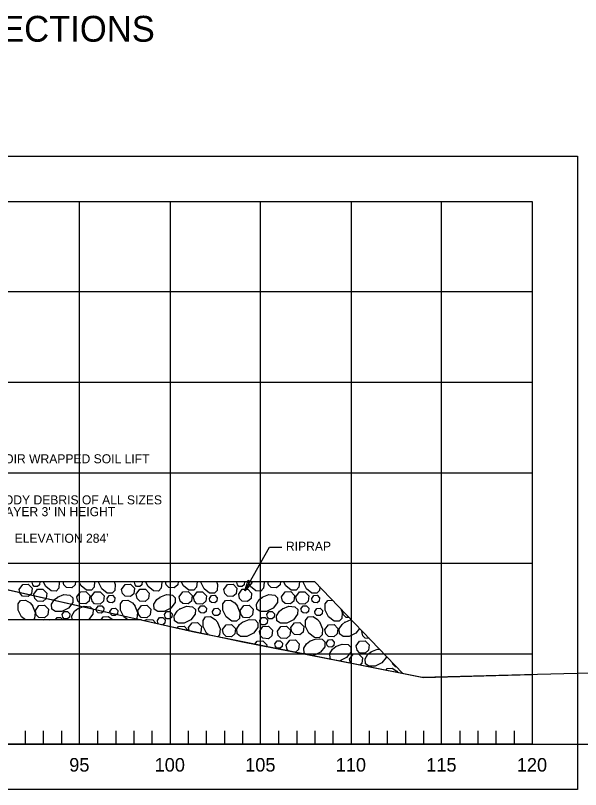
# Model space of a CAD drawing. Extents: x 1578769 to 1579225, y 724002 to 724828.
# Drawn here: x 1578895.66 to 1578926.86, y 724300.65 to 724343.43 of the extents above; entities that cross this region are included whole.
import ezdxf

# ---------------------------------------------------------------- set-up
doc = ezdxf.new("R2010")
doc.units = 0
for name, color, linetype in [('1', 7, 'Continuous'), ('Default', 7, 'Continuous'), ('Old_Level_1', 7, 'Continuous'), ('Old_Level_41', 7, 'Continuous'), ('Old_Level_42', 7, 'Continuous'), ('R_Exist Surface', 7, 'Continuous'), ('R_Rip-Rap', 7, 'Continuous')]:
    doc.layers.add(name, color=color, linetype=linetype)

msp = doc.modelspace()

# ---------------------------------------------------------------- linework, layer by layer
at = {"layer": '1'}
msp.add_lwpolyline([(1578908.325, 724311.631), (1578909.693, 724314.045), (1578910.378, 724314.045)], dxfattribs=at)
msp.add_lwpolyline([(1578908.725, 724312.094), (1578908.325, 724311.631), (1578908.516, 724312.212)], close=True, dxfattribs=at)
at = {"layer": 'Default'}
msp.add_line((1578824.194, 724303.15), (1579224.194, 724303.15), dxfattribs=at)
msp.add_lwpolyline([(1578822.944, 724322.15), (1578824.354, 724322.105), (1578827.254, 724322.088), (1578831.424, 724322.063), (1578836.824, 724322.031), (1578858.594, 724322.068), (1578861.134, 724322.067), (1578862.944, 724322.071), (1578882.454, 724322.012), (1578884.524, 724320.413), (1578890.394, 724312.796), (1578905.444, 724309.389), (1578918.124, 724306.852), (1578923.764, 724306.998), (1578939.004, 724307.393), (1578947.244, 724307.607), (1578961.874, 724307.852), (1578966.594, 724307.868), (1579023.724, 724312.412), (1579059.084, 724315.375), (1579126.244, 724320.038), (1579145.794, 724321.276)], dxfattribs=at)
at = {"layer": 'Old_Level_1'}
for points in [[(1578819.194, 724335.65), (1578926.694, 724335.65), (1578926.694, 724300.65), (1578819.194, 724300.65)], [(1578824.194, 724333.15), (1578924.194, 724333.15), (1578924.194, 724303.15), (1578824.194, 724303.15)]]:
    msp.add_lwpolyline(points, close=True, dxfattribs=at)
at = {"layer": 'Old_Level_41'}
for p, q in [((1578899.194, 724303.15), (1578899.194, 724333.15)), ((1578904.194, 724333.15), (1578904.194, 724303.15)), ((1578909.194, 724303.15), (1578909.194, 724333.15)), ((1578914.194, 724333.15), (1578914.194, 724303.15)), ((1578919.194, 724303.15), (1578919.194, 724333.15))]:
    msp.add_line(p, q, dxfattribs=at)
for points in [[(1578924.194, 724328.15), (1578824.194, 724328.15)], [(1578924.194, 724323.15), (1578824.194, 724323.15)], [(1578824.194, 724318.15), (1578924.194, 724318.15)], [(1578924.194, 724313.15), (1578824.194, 724313.15)], [(1578824.194, 724308.15), (1578924.194, 724308.15)]]:
    msp.add_lwpolyline(points, dxfattribs=at)
at = {"layer": 'Old_Level_42'}
for p, q in [((1578896.194, 724303.9), (1578896.194, 724303.15)), ((1578897.194, 724303.9), (1578897.194, 724303.15)), ((1578898.194, 724303.9), (1578898.194, 724303.15)), ((1578900.194, 724303.9), (1578900.194, 724303.15)), ((1578901.194, 724303.9), (1578901.194, 724303.15)), ((1578902.194, 724303.9), (1578902.194, 724303.15)), ((1578903.194, 724303.9), (1578903.194, 724303.15)), ((1578905.194, 724303.9), (1578905.194, 724303.15)), ((1578906.194, 724303.9), (1578906.194, 724303.15)), ((1578907.194, 724303.9), (1578907.194, 724303.15)), ((1578908.194, 724303.9), (1578908.194, 724303.15)), ((1578910.194, 724303.9), (1578910.194, 724303.15)), ((1578911.194, 724303.9), (1578911.194, 724303.15)), ((1578912.194, 724303.9), (1578912.194, 724303.15)), ((1578913.194, 724303.9), (1578913.194, 724303.15)), ((1578915.194, 724303.9), (1578915.194, 724303.15)), ((1578916.194, 724303.9), (1578916.194, 724303.15)), ((1578917.194, 724303.9), (1578917.194, 724303.15)), ((1578918.194, 724303.9), (1578918.194, 724303.15)), ((1578920.194, 724303.9), (1578920.194, 724303.15)), ((1578921.194, 724303.9), (1578921.194, 724303.15)), ((1578922.194, 724303.9), (1578922.194, 724303.15)), ((1578923.194, 724303.9), (1578923.194, 724303.15))]:
    msp.add_line(p, q, dxfattribs=at)
at = {"layer": 'R_Exist Surface'}
msp.add_lwpolyline([(1578824.194, 724322.162), (1578829.284, 724322.091), (1578836.275, 724322.056), (1578841.243, 724322.049), (1578852.243, 724322.048), (1578866.252, 724322.093), (1578877.209, 724322.014), (1578882.216, 724322.036), (1578883.229, 724321.428), (1578884.216, 724320.636), (1578885.259, 724319.504), (1578887.377, 724316.691), (1578890.502, 724312.788), (1578895.252, 724311.694), (1578904.139, 724309.679), (1578908.201, 724308.813), (1578914.491, 724307.577), (1578918.186, 724306.844), (1578924.194, 724307.012)], dxfattribs=at)
at = {"layer": 'R_Rip-Rap'}
for p, q in [((1578893.271, 724312.15), (1578912.174, 724312.15)), ((1578896.581, 724312.101), (1578896.616, 724312.15)), ((1578902.234, 724312.101), (1578902.269, 724312.15)), ((1578907.888, 724312.101), (1578907.922, 724312.15)), ((1578912.174, 724312.15), (1578917.048, 724307.07)), ((1578902.612, 724310.025), (1578889.194, 724310.025)), ((1578902.612, 724310.025), (1578902.612, 724310.025)), ((1578913.859, 724309.906), (1578914.198, 724310.041)), ((1578905.248, 724309.443), (1578905.219, 724309.595)), ((1578914.789, 724309.384), (1578914.806, 724309.407)), ((1578914.155, 724307.643), (1578914.113, 724307.861))]:
    msp.add_line(p, q, dxfattribs=at)
for points in [[(1578897.001, 724312.15), (1578897.008, 724312.142), (1578896.99, 724311.957), (1578896.876, 724311.862), (1578896.694, 724311.875), (1578896.609, 724311.958), (1578896.581, 724312.101)], [(1578898.063, 724312.15), (1578898.08, 724312.108), (1578898.051, 724311.778), (1578897.902, 724311.621), (1578897.634, 724311.626), (1578897.33, 724311.864), (1578897.187, 724312.15)], [(1578898.983, 724312.15), (1578898.963, 724311.956), (1578898.774, 724311.798), (1578898.471, 724311.82), (1578898.329, 724311.958), (1578898.291, 724312.15)], [(1578900.031, 724312.15), (1578900.003, 724311.825), (1578899.854, 724311.668), (1578899.586, 724311.673), (1578899.282, 724311.911), (1578899.162, 724312.15)], [(1578901.103, 724312.15), (1578901.171, 724311.98), (1578901.142, 724311.65), (1578900.993, 724311.493), (1578900.725, 724311.498), (1578900.421, 724311.737), (1578900.237, 724312.105), (1578900.236, 724312.15)], [(1578902.654, 724312.15), (1578902.661, 724312.142), (1578902.643, 724311.957), (1578902.529, 724311.862), (1578902.348, 724311.875), (1578902.262, 724311.958), (1578902.234, 724312.101)], [(1578903.717, 724312.15), (1578903.733, 724312.108), (1578903.705, 724311.778), (1578903.555, 724311.621), (1578903.288, 724311.626), (1578902.983, 724311.864), (1578902.84, 724312.15)], [(1578904.636, 724312.15), (1578904.617, 724311.956), (1578904.427, 724311.798), (1578904.125, 724311.82), (1578903.982, 724311.958), (1578903.945, 724312.15)], [(1578905.685, 724312.15), (1578905.657, 724311.825), (1578905.508, 724311.668), (1578905.24, 724311.673), (1578904.935, 724311.911), (1578904.816, 724312.15)], [(1578906.757, 724312.15), (1578906.824, 724311.98), (1578906.796, 724311.65), (1578906.646, 724311.493), (1578906.379, 724311.498), (1578906.074, 724311.737), (1578905.89, 724312.105), (1578905.89, 724312.15)], [(1578908.308, 724312.15), (1578908.315, 724312.142), (1578908.296, 724311.957), (1578908.183, 724311.862), (1578908.001, 724311.875), (1578907.916, 724311.958), (1578907.888, 724312.101)], [(1578909.37, 724312.15), (1578909.387, 724312.108), (1578909.358, 724311.778), (1578909.209, 724311.621), (1578908.941, 724311.626), (1578908.637, 724311.864), (1578908.494, 724312.15)], [(1578910.29, 724312.15), (1578910.27, 724311.956), (1578910.081, 724311.798), (1578909.778, 724311.82), (1578909.636, 724311.958), (1578909.598, 724312.15)], [(1578911.338, 724312.15), (1578911.31, 724311.825), (1578911.161, 724311.668), (1578910.893, 724311.673), (1578910.589, 724311.911), (1578910.469, 724312.15)], [(1578912.466, 724311.846), (1578912.449, 724311.65), (1578912.3, 724311.493), (1578912.032, 724311.498), (1578911.728, 724311.737), (1578911.544, 724312.105), (1578911.543, 724312.15)], [(1578895.867, 724311.712), (1578896.059, 724311.985), (1578896.366, 724312.002), (1578896.579, 724311.781), (1578896.548, 724311.472), (1578896.359, 724311.314), (1578896.056, 724311.336), (1578895.913, 724311.474), (1578895.867, 724311.712)], [(1578896.679, 724311.44), (1578896.871, 724311.714), (1578897.177, 724311.731), (1578897.391, 724311.51), (1578897.36, 724311.2), (1578897.17, 724311.043), (1578896.868, 724311.065), (1578896.725, 724311.203), (1578896.679, 724311.44)], [(1578901.521, 724311.712), (1578901.713, 724311.985), (1578902.019, 724312.002), (1578902.232, 724311.781), (1578902.202, 724311.472), (1578902.012, 724311.314), (1578901.709, 724311.336), (1578901.567, 724311.474), (1578901.521, 724311.712)], [(1578902.332, 724311.44), (1578902.524, 724311.714), (1578902.831, 724311.731), (1578903.044, 724311.51), (1578903.013, 724311.2), (1578902.824, 724311.043), (1578902.521, 724311.065), (1578902.379, 724311.203), (1578902.332, 724311.44)], [(1578907.174, 724311.712), (1578907.366, 724311.985), (1578907.673, 724312.002), (1578907.886, 724311.781), (1578907.855, 724311.472), (1578907.666, 724311.314), (1578907.363, 724311.336), (1578907.22, 724311.474), (1578907.174, 724311.712)], [(1578907.986, 724311.44), (1578908.178, 724311.714), (1578908.484, 724311.731), (1578908.698, 724311.51), (1578908.667, 724311.2), (1578908.477, 724311.043), (1578908.174, 724311.065), (1578908.032, 724311.203), (1578907.986, 724311.44)], [(1578897.98, 724311.28), (1578898.339, 724311.422), (1578898.669, 724311.394), (1578898.826, 724311.245), (1578898.821, 724310.977), (1578898.583, 724310.673), (1578898.215, 724310.489), (1578897.868, 724310.482), (1578897.673, 724310.621), (1578897.654, 724310.897), (1578897.813, 724311.144), (1578897.994, 724311.289)], [(1578899.051, 724311.305), (1578899.243, 724311.578), (1578899.55, 724311.596), (1578899.763, 724311.375), (1578899.732, 724311.065), (1578899.543, 724310.907), (1578899.24, 724310.929), (1578899.097, 724311.067), (1578899.051, 724311.305)], [(1578899.841, 724311.293), (1578900.033, 724311.567), (1578900.34, 724311.584), (1578900.553, 724311.363), (1578900.522, 724311.053), (1578900.333, 724310.896), (1578900.03, 724310.918), (1578899.888, 724311.056), (1578899.841, 724311.293)], [(1578900.715, 724311.209), (1578900.83, 724311.373), (1578901.014, 724311.383), (1578901.142, 724311.251), (1578901.124, 724311.065), (1578901.01, 724310.97), (1578900.828, 724310.984), (1578900.743, 724311.066), (1578900.715, 724311.209)], [(1578903.633, 724311.28), (1578903.992, 724311.422), (1578904.322, 724311.394), (1578904.479, 724311.245), (1578904.474, 724310.977), (1578904.236, 724310.673), (1578903.868, 724310.489), (1578903.521, 724310.482), (1578903.326, 724310.621), (1578903.308, 724310.897), (1578903.466, 724311.144), (1578903.647, 724311.289)], [(1578904.704, 724311.305), (1578904.896, 724311.578), (1578905.203, 724311.596), (1578905.416, 724311.375), (1578905.385, 724311.065), (1578905.196, 724310.907), (1578904.893, 724310.929), (1578904.751, 724311.067), (1578904.705, 724311.305)], [(1578905.495, 724311.293), (1578905.687, 724311.567), (1578905.993, 724311.584), (1578906.207, 724311.363), (1578906.176, 724311.053), (1578905.986, 724310.896), (1578905.683, 724310.918), (1578905.541, 724311.056), (1578905.495, 724311.293)], [(1578906.369, 724311.209), (1578906.484, 724311.373), (1578906.668, 724311.383), (1578906.796, 724311.251), (1578906.777, 724311.065), (1578906.664, 724310.97), (1578906.482, 724310.984), (1578906.396, 724311.066), (1578906.369, 724311.209)], [(1578909.286, 724311.28), (1578909.646, 724311.422), (1578909.976, 724311.394), (1578910.133, 724311.245), (1578910.128, 724310.977), (1578909.89, 724310.673), (1578909.522, 724310.489), (1578909.175, 724310.482), (1578908.98, 724310.621), (1578908.961, 724310.897), (1578909.12, 724311.144), (1578909.301, 724311.289)], [(1578910.358, 724311.305), (1578910.55, 724311.578), (1578910.857, 724311.596), (1578911.07, 724311.375), (1578911.039, 724311.065), (1578910.849, 724310.907), (1578910.547, 724310.929), (1578910.404, 724311.067), (1578910.358, 724311.305)], [(1578911.148, 724311.293), (1578911.34, 724311.567), (1578911.647, 724311.584), (1578911.86, 724311.363), (1578911.829, 724311.053), (1578911.64, 724310.896), (1578911.337, 724310.918), (1578911.194, 724311.056), (1578911.148, 724311.293)], [(1578912.022, 724311.209), (1578912.137, 724311.373), (1578912.321, 724311.383), (1578912.449, 724311.251), (1578912.431, 724311.065), (1578912.317, 724310.97), (1578912.135, 724310.984), (1578912.05, 724311.066), (1578912.022, 724311.209)], [(1578896.205, 724310.025), (1578895.993, 724310.191), (1578895.81, 724310.559), (1578895.803, 724310.906), (1578895.942, 724311.101), (1578896.218, 724311.12), (1578896.465, 724310.961), (1578896.61, 724310.78)], [(1578896.764, 724310.541), (1578896.956, 724310.815), (1578897.263, 724310.832), (1578897.476, 724310.611), (1578897.445, 724310.301), (1578897.256, 724310.144), (1578896.953, 724310.166), (1578896.811, 724310.304), (1578896.764, 724310.541)], [(1578901.859, 724310.025), (1578901.647, 724310.191), (1578901.463, 724310.559), (1578901.457, 724310.906), (1578901.596, 724311.101), (1578901.872, 724311.12), (1578902.119, 724310.961), (1578902.264, 724310.78)], [(1578902.418, 724310.541), (1578902.61, 724310.815), (1578902.916, 724310.832), (1578903.13, 724310.611), (1578903.099, 724310.301), (1578902.909, 724310.144), (1578902.606, 724310.166), (1578902.464, 724310.304), (1578902.418, 724310.541)], [(1578907.908, 724310.794), (1578908.05, 724310.435), (1578908.022, 724310.105), (1578907.873, 724309.948), (1578907.605, 724309.953), (1578907.3, 724310.191), (1578907.116, 724310.559), (1578907.11, 724310.906), (1578907.249, 724311.101), (1578907.525, 724311.12), (1578907.772, 724310.961), (1578907.917, 724310.78)], [(1578908.071, 724310.541), (1578908.263, 724310.815), (1578908.57, 724310.832), (1578908.783, 724310.611), (1578908.752, 724310.301), (1578908.563, 724310.144), (1578908.26, 724310.166), (1578908.117, 724310.304), (1578908.071, 724310.541)], [(1578913.622, 724310.641), (1578913.704, 724310.435), (1578913.675, 724310.105), (1578913.526, 724309.948), (1578913.258, 724309.953), (1578912.954, 724310.191), (1578912.77, 724310.559), (1578912.764, 724310.906), (1578912.902, 724311.101), (1578913.164, 724311.119)], [(1578896.601, 724310.794), (1578896.743, 724310.435), (1578896.715, 724310.105), (1578896.639, 724310.025)], [(1578898.238, 724310.317), (1578898.353, 724310.481), (1578898.537, 724310.492), (1578898.665, 724310.359), (1578898.647, 724310.173), (1578898.533, 724310.079), (1578898.351, 724310.092), (1578898.266, 724310.175), (1578898.238, 724310.317)], [(1578898.785, 724310.025), (1578898.769, 724310.256), (1578898.927, 724310.503), (1578899.109, 724310.647)], [(1578899.094, 724310.638), (1578899.454, 724310.781), (1578899.784, 724310.752), (1578899.941, 724310.603), (1578899.936, 724310.335), (1578899.698, 724310.031), (1578899.687, 724310.025)], [(1578900.121, 724310.632), (1578900.236, 724310.796), (1578900.42, 724310.807), (1578900.548, 724310.674), (1578900.529, 724310.488), (1578900.416, 724310.394), (1578900.234, 724310.407), (1578900.148, 724310.49), (1578900.121, 724310.632)], [(1578900.877, 724310.497), (1578900.992, 724310.661), (1578901.176, 724310.672), (1578901.304, 724310.539), (1578901.286, 724310.353), (1578901.172, 724310.259), (1578900.991, 724310.272), (1578900.905, 724310.355), (1578900.877, 724310.497)], [(1578902.254, 724310.794), (1578902.397, 724310.435), (1578902.368, 724310.105), (1578902.293, 724310.025)], [(1578903.892, 724310.317), (1578904.007, 724310.481), (1578904.191, 724310.492), (1578904.319, 724310.359), (1578904.3, 724310.173), (1578904.187, 724310.079), (1578904.005, 724310.092), (1578903.919, 724310.175), (1578903.892, 724310.317)], [(1578904.748, 724310.638), (1578905.107, 724310.781), (1578905.437, 724310.752), (1578905.594, 724310.603), (1578905.589, 724310.335), (1578905.351, 724310.031), (1578904.983, 724309.847), (1578904.636, 724309.841), (1578904.441, 724309.979), (1578904.423, 724310.256), (1578904.581, 724310.503), (1578904.762, 724310.647)], [(1578905.774, 724310.632), (1578905.889, 724310.796), (1578906.073, 724310.807), (1578906.201, 724310.674), (1578906.183, 724310.488), (1578906.069, 724310.394), (1578905.887, 724310.407), (1578905.802, 724310.49), (1578905.774, 724310.632)], [(1578906.531, 724310.497), (1578906.646, 724310.661), (1578906.83, 724310.672), (1578906.958, 724310.539), (1578906.939, 724310.353), (1578906.826, 724310.259), (1578906.644, 724310.272), (1578906.558, 724310.355), (1578906.531, 724310.497)], [(1578909.545, 724310.317), (1578909.66, 724310.481), (1578909.844, 724310.492), (1578909.972, 724310.359), (1578909.954, 724310.173), (1578909.84, 724310.079), (1578909.658, 724310.092), (1578909.573, 724310.175), (1578909.545, 724310.317)], [(1578910.401, 724310.638), (1578910.761, 724310.781), (1578911.091, 724310.752), (1578911.248, 724310.603), (1578911.243, 724310.335), (1578911.004, 724310.031), (1578910.636, 724309.847), (1578910.29, 724309.841), (1578910.094, 724309.979), (1578910.076, 724310.256), (1578910.234, 724310.503), (1578910.416, 724310.647)], [(1578911.427, 724310.632), (1578911.543, 724310.796), (1578911.727, 724310.807), (1578911.855, 724310.674), (1578911.836, 724310.488), (1578911.722, 724310.394), (1578911.541, 724310.407), (1578911.455, 724310.49), (1578911.428, 724310.632)], [(1578912.184, 724310.497), (1578912.299, 724310.661), (1578912.483, 724310.672), (1578912.611, 724310.539), (1578912.593, 724310.353), (1578912.479, 724310.259), (1578912.297, 724310.272), (1578912.212, 724310.355), (1578912.184, 724310.497)], [(1578914.09, 724310.153), (1578913.913, 724310.166), (1578913.771, 724310.304), (1578913.726, 724310.532)], [(1578897.199, 724310.025), (1578897.258, 724310.049), (1578897.526, 724310.025)], [(1578897.871, 724310.025), (1578897.957, 724310.148), (1578898.141, 724310.158), (1578898.269, 724310.026), (1578898.269, 724310.025)], [(1578900.388, 724310.025), (1578900.509, 724310.195), (1578900.785, 724310.213), (1578901.032, 724310.055), (1578901.056, 724310.025)], [(1578902.765, 724309.991), (1578902.911, 724310.049), (1578903.241, 724310.02), (1578903.398, 724309.871), (1578903.398, 724309.847)], [(1578903.495, 724309.984), (1578903.611, 724310.148), (1578903.795, 724310.158), (1578903.922, 724310.026), (1578903.904, 724309.84), (1578903.802, 724309.756)], [(1578903.554, 724309.812), (1578903.523, 724309.841), (1578903.495, 724309.984)], [(1578906.298, 724309.219), (1578906.213, 724309.285), (1578906.03, 724309.653), (1578906.023, 724309.999), (1578906.162, 724310.195), (1578906.438, 724310.213), (1578906.685, 724310.055), (1578906.83, 724309.873)], [(1578908.205, 724309.906), (1578908.565, 724310.049), (1578908.895, 724310.02), (1578909.052, 724309.871), (1578909.047, 724309.603), (1578908.808, 724309.299), (1578908.441, 724309.115), (1578908.094, 724309.109), (1578907.899, 724309.247), (1578907.88, 724309.524), (1578908.038, 724309.771), (1578908.22, 724309.915)], [(1578909.149, 724309.984), (1578909.264, 724310.148), (1578909.448, 724310.158), (1578909.576, 724310.026), (1578909.557, 724309.84), (1578909.444, 724309.745), (1578909.262, 724309.759), (1578909.177, 724309.841), (1578909.149, 724309.984)], [(1578912.474, 724309.888), (1578912.617, 724309.529), (1578912.588, 724309.198), (1578912.439, 724309.042), (1578912.171, 724309.047), (1578911.867, 724309.285), (1578911.683, 724309.653), (1578911.677, 724309.999), (1578911.816, 724310.195), (1578912.092, 724310.213), (1578912.339, 724310.055), (1578912.484, 724309.873)], [(1578904.604, 724309.58), (1578904.666, 724309.668), (1578904.972, 724309.686), (1578905.185, 724309.465), (1578905.185, 724309.456)], [(1578905.218, 724309.595), (1578905.41, 724309.868), (1578905.717, 724309.886), (1578905.93, 724309.665), (1578905.9, 724309.355), (1578905.85, 724309.314)], [(1578906.821, 724309.888), (1578906.963, 724309.529), (1578906.935, 724309.198), (1578906.844, 724309.102)], [(1578907.098, 724309.485), (1578907.29, 724309.758), (1578907.596, 724309.776), (1578907.81, 724309.555), (1578907.779, 724309.245), (1578907.589, 724309.087), (1578907.286, 724309.109), (1578907.144, 724309.247), (1578907.098, 724309.485)], [(1578909.136, 724309.384), (1578909.328, 724309.657), (1578909.635, 724309.674), (1578909.848, 724309.453), (1578909.817, 724309.143), (1578909.628, 724308.986), (1578909.325, 724309.008), (1578909.182, 724309.146), (1578909.136, 724309.383)], [(1578910.127, 724309.395), (1578910.319, 724309.668), (1578910.626, 724309.686), (1578910.839, 724309.465), (1578910.808, 724309.155), (1578910.619, 724308.997), (1578910.316, 724309.019), (1578910.173, 724309.157), (1578910.127, 724309.395)], [(1578910.872, 724309.595), (1578911.064, 724309.868), (1578911.371, 724309.886), (1578911.584, 724309.665), (1578911.553, 724309.355), (1578911.363, 724309.198), (1578911.061, 724309.22), (1578910.918, 724309.358), (1578910.872, 724309.595)], [(1578912.751, 724309.485), (1578912.943, 724309.758), (1578913.25, 724309.776), (1578913.463, 724309.555), (1578913.432, 724309.245), (1578913.243, 724309.087), (1578912.94, 724309.109), (1578912.797, 724309.247), (1578912.751, 724309.485)], [(1578914.663, 724309.556), (1578914.462, 724309.299), (1578914.094, 724309.115), (1578913.747, 724309.109), (1578913.552, 724309.247), (1578913.533, 724309.524), (1578913.692, 724309.771), (1578913.873, 724309.915)], [(1578915.204, 724308.991), (1578914.978, 724309.008), (1578914.836, 724309.146), (1578914.79, 724309.383)], [(1578908.887, 724308.678), (1578909.013, 724308.857), (1578909.32, 724308.874), (1578909.533, 724308.653), (1578909.523, 724308.553)], [(1578909.986, 724308.696), (1578910.102, 724308.86), (1578910.286, 724308.87), (1578910.414, 724308.738), (1578910.395, 724308.552), (1578910.281, 724308.457), (1578910.1, 724308.47), (1578910.014, 724308.553), (1578909.986, 724308.696)], [(1578910.616, 724308.625), (1578910.808, 724308.898), (1578911.115, 724308.916), (1578911.328, 724308.695), (1578911.297, 724308.385), (1578911.121, 724308.239)], [(1578911.675, 724308.13), (1578911.598, 724308.185), (1578911.579, 724308.461), (1578911.738, 724308.708), (1578911.919, 724308.853)], [(1578911.905, 724308.843), (1578912.264, 724308.986), (1578912.594, 724308.957), (1578912.751, 724308.808), (1578912.746, 724308.54), (1578912.508, 724308.236), (1578912.14, 724308.052), (1578912.078, 724308.051)], [(1578912.839, 724308.759), (1578912.954, 724308.923), (1578913.138, 724308.933), (1578913.266, 724308.801), (1578913.247, 724308.615), (1578913.134, 724308.52), (1578912.952, 724308.533), (1578912.866, 724308.616), (1578912.839, 724308.759)], [(1578913.336, 724308.548), (1578913.696, 724308.691), (1578914.026, 724308.662), (1578914.183, 724308.513), (1578914.178, 724308.245), (1578913.939, 724307.941), (1578913.572, 724307.757)], [(1578914.474, 724308.583), (1578914.666, 724308.857), (1578914.973, 724308.874), (1578915.186, 724308.653), (1578915.155, 724308.343), (1578914.966, 724308.186), (1578914.663, 724308.208), (1578914.521, 724308.346), (1578914.474, 724308.583)], [(1578910.738, 724308.315), (1578910.662, 724308.387), (1578910.616, 724308.625)], [(1578913.08, 724307.854), (1578913.03, 724307.89), (1578913.011, 724308.166), (1578913.169, 724308.413), (1578913.351, 724308.558)], [(1578916.131, 724308.025), (1578916.13, 724307.955), (1578915.892, 724307.651), (1578915.524, 724307.467), (1578915.177, 724307.46), (1578914.982, 724307.599), (1578914.963, 724307.875), (1578915.122, 724308.122), (1578915.303, 724308.267)], [(1578915.288, 724308.258), (1578915.648, 724308.4), (1578915.783, 724308.389)], [(1578914.113, 724307.861), (1578914.305, 724308.134), (1578914.612, 724308.151), (1578914.825, 724307.93), (1578914.794, 724307.621), (1578914.693, 724307.537)], [(1578916.706, 724307.427), (1578916.639, 724307.431), (1578916.496, 724307.569), (1578916.478, 724307.664)], [(1578916.131, 724307.252), (1578916.191, 724307.335), (1578916.467, 724307.354), (1578916.714, 724307.196), (1578916.771, 724307.125)]]:
    msp.add_lwpolyline(points, dxfattribs=at)

# ---------------------------------------------------------------- texts
at = {"layer": '1'}
for s, height, p in [("1' COIR WRAPPED SOIL LIFT", 0.5, (1578893.868, 724318.678)), ('WOODY DEBRIS OF ALL SIZES', 0.5, (1578893.868, 724316.408)), ("IN LAYER 3' IN HEIGHT", 0.5, (1578893.868, 724315.757)), ("ELEVATION 284'", 0.5, (1578895.615, 724314.286)), ('RIPRAP', 0.5, (1578910.596, 724313.845)), ('95', 0.75, (1578898.628, 724301.64)), ('100', 0.75, (1578903.344, 724301.64)), ('105', 0.75, (1578908.344, 724301.64)), ('110', 0.75, (1578913.344, 724301.64)), ('115', 0.75, (1578918.344, 724301.64)), ('120', 0.75, (1578923.344, 724301.64))]:
    msp.add_text(s, height=height, dxfattribs=at).set_placement(p)
at = {"layer": 'Old_Level_1'}
msp.add_text('TYPICAL RIFFLE, POOL, AND BANKFULL BENCH CROSS SECTIONS', height=1.42857, dxfattribs=at).set_placement((1578841.574, 724341.978))

doc.saveas('drawing.dxf')
